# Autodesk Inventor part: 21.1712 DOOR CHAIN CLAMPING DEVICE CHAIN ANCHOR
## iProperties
Created: 2007-05
Part Number: 21.1712 DOOR CHAIN CLAMPING DEVICE CHAIN ANCHOR
Material: Steel
Document SubType Name: Modeling
Designer: Andy Moles
Mass: 7.21146 g
Surface Area: 6.45496 cm^2
Volume: 0.918657 cm^3
Density: 7.85 g/cm^3
Author: Andy Moles
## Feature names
1. Revolution1
2. Extrusion1
3. Extrusion2
